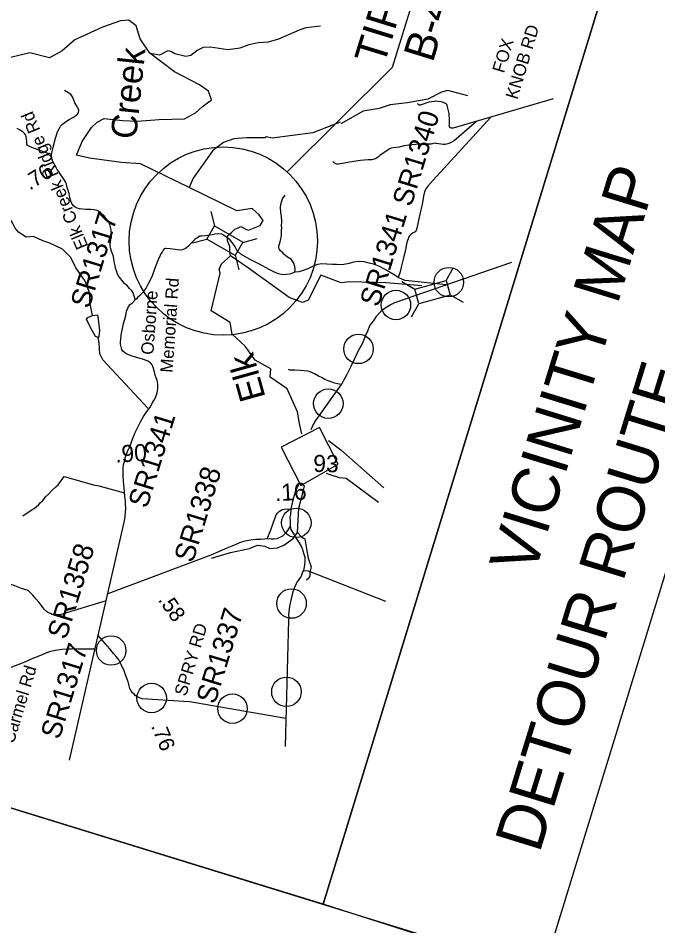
# Model space of a CAD drawing. Extents: x 1348011 to 1349268, y 1028333 to 1030014.
# Drawn here: x 1348154.1 to 1348346.3, y 1028708.2 to 1028980.8 of the extents above; entities that cross this region are included whole.
import ezdxf

# ---------------------------------------------------------------- set-up
doc = ezdxf.new("R2010")
doc.units = 0
for name, color, linetype in [('Prop Leader Line Light', 7, 'Continuous'), ('Prop Leader Line Medium', 7, 'Continuous'), ('Prop WCC CELL', 7, 'Continuous'), ('Scratch_Level_3', 7, 'Continuous'), ('Sheet Data Field CELL', 7, 'Continuous'), ('Sheet Symbology CELL', 7, 'Continuous')]:
    doc.layers.add(name, color=color, linetype=linetype)

msp = doc.modelspace()

# ---------------------------------------------------------------- linework, layer by layer
at = {"layer": 'Prop Leader Line Light'}
msp.add_lwpolyline([(1348302.35, 1028907.44), (1348267.14, 1028895.27), (1348266.17, 1028894.75), (1348264.42, 1028893.66), (1348263.06, 1028892.64), (1348261.7, 1028891.15), (1348260.73, 1028889.82), (1348259.82, 1028888.53), (1348259.04, 1028886.76), (1348258.46, 1028885.46), (1348257.43, 1028882.98), (1348256.2, 1028880.62), (1348255.1, 1028878.23), (1348253.98, 1028875.93), (1348252.76, 1028873.57), (1348251.78, 1028871.72), (1348251.42, 1028871.13), (1348251.18, 1028870.75), (1348243.41, 1028859.89), (1348242.72, 1028858.78), (1348242, 1028857.16)], dxfattribs=at)
for centre in [(1348283.51, 1028901.5), (1348267.61, 1028894.63), (1348256.37, 1028881.44), (1348247.29, 1028865.01), (1348237.7, 1028829.2), (1348236.26, 1028804.96), (1348182.07, 1028790.85), (1348234.71, 1028778.45), (1348194.21, 1028776.57), (1348218.5, 1028773.39)]:
    msp.add_circle(centre, 4.43, dxfattribs=at)
at = {"layer": 'Prop Leader Line Medium'}
for p, q in [((1348287.74, 1029034.54), (1348266.45, 1028965.92)), ((1348234.94, 1028934.6), (1348266.45, 1028965.92)), ((1348211.96, 1028922.74), (1348213.1, 1028918.41)), ((1348206.46, 1028913.31), (1348210.79, 1028914.45)), ((1348221.57, 1028913.44), (1348225.91, 1028914.58)), ((1348219.31, 1028909.57), (1348220.45, 1028905.23)), ((1348282.73, 1028902.01), (1348284.95, 1028905.9)), ((1348269.36, 1028901.64), (1348273.26, 1028899.43)), ((1348283.92, 1028897.68), (1348287.81, 1028895.46)), ((1348272.25, 1028891.11), (1348274.47, 1028895))]:
    msp.add_line(p, q, dxfattribs=at)
for points in [[(1348205.49, 1028929.9), (1348190.92, 1028937.03), (1348185.2, 1028937.42), (1348175.52, 1028938.7), (1348171.65, 1028939.62), (1348173.33, 1028943.77), (1348176.1, 1028947.9), (1348177.88, 1028949.58), (1348179.93, 1028950.63), (1348185.5, 1028950), (1348189.95, 1028949.82), (1348196.45, 1028950.36), (1348204.13, 1028950.58), (1348207.38, 1028952.32), (1348209.44, 1028954.13), (1348212.17, 1028956.21), (1348211.28, 1028958.89), (1348208.62, 1028960.8), (1348201.09, 1028964.63), (1348193.63, 1028970.29), (1348190.8, 1028974.54), (1348189.55, 1028978.48), (1348187.34, 1028980.13), (1348184.87, 1028980.02), (1348179.41, 1028978.04), (1348171.14, 1028974.26), (1348167.31, 1028970.94), (1348163.53, 1028968.84), (1348157.6, 1028970.38), (1348151.43, 1028968.83)], [(1348193.63, 1028970.29), (1348196.7, 1028969.77), (1348199.2, 1028971.04), (1348200.17, 1028970.81), (1348201.21, 1028970.17), (1348204.48, 1028969.32), (1348205.96, 1028969.67), (1348207.75, 1028971.05), (1348209.75, 1028972.06), (1348211.91, 1028972.19), (1348217.15, 1028971.36), (1348220.84, 1028971.82), (1348223.5, 1028972.83), (1348226.18, 1028973.5), (1348229.35, 1028973.64), (1348232.45, 1028974.58), (1348238.68, 1028977.31), (1348240.69, 1028977.99), (1348244.93, 1028978.48)], [(1348189.28, 1028896.17), (1348189.04, 1028897.12), (1348188.91, 1028897.62), (1348188.66, 1028898.27), (1348188.27, 1028898.85), (1348187.6, 1028899.59), (1348186.81, 1028900.55), (1348186.12, 1028901.02), (1348185.55, 1028901.7), (1348185.02, 1028902.37), (1348184.4, 1028903.17), (1348183.99, 1028903.94), (1348183.68, 1028904.9), (1348183.41, 1028905.74), (1348183.28, 1028906.43), (1348183.08, 1028907.23), (1348182.83, 1028908.43), (1348182.75, 1028909.22), (1348182.43, 1028910.03), (1348182.18, 1028910.76), (1348181.86, 1028911.78), (1348181.8, 1028912.61), (1348181.83, 1028913.67), (1348182.11, 1028915.08), (1348182.15, 1028916.01), (1348181.96, 1028917.63), (1348181.54, 1028919.2), (1348180.49, 1028920.74), (1348179.95, 1028921.38), (1348178.87, 1028922.4), (1348177.88, 1028923), (1348176.83, 1028923.24), (1348175.81, 1028923.34), (1348174.46, 1028923.36), (1348173.47, 1028923.44), (1348172.59, 1028923.56), (1348171.83, 1028923.69), (1348171.22, 1028924.05), (1348170.66, 1028924.5), (1348170.26, 1028925.13), (1348169.99, 1028925.77), (1348169.68, 1028926.88), (1348169.48, 1028928.13), (1348168.98, 1028929.61), (1348168.76, 1028930.18), (1348168.59, 1028931.02), (1348168.31, 1028931.66), (1348167.82, 1028932.45), (1348167.41, 1028933), (1348166.89, 1028933.7), (1348166.16, 1028934.9), (1348165.85, 1028935.34), (1348165.49, 1028935.94), (1348164.99, 1028936.82), (1348164.79, 1028937.22), (1348164.54, 1028937.69), (1348164.34, 1028938.34), (1348164.12, 1028939.07), (1348164.16, 1028939.44), (1348164.17, 1028939.87), (1348164.67, 1028941.99), (1348165.37, 1028944.75), (1348165.97, 1028946.64), (1348166.39, 1028947.58), (1348166.85, 1028948.32), (1348167.32, 1028948.86), (1348167.9, 1028949.3), (1348168.61, 1028949.82), (1348169.49, 1028950.32), (1348170.74, 1028951.03), (1348171.84, 1028951.87), (1348172.12, 1028952.23), (1348172.24, 1028952.36), (1348172.39, 1028953.12), (1348171.86, 1028954.23), (1348171.41, 1028954.84), (1348171.11, 1028955.37), (1348170.82, 1028956.2), (1348170.49, 1028957.18), (1348170.05, 1028957.74), (1348169.21, 1028958.33), (1348168.03, 1028959.04)], [(1348289.17, 1028957.45), (1348283.23, 1028959.02), (1348281.32, 1028958.6), (1348277.21, 1028956.47), (1348271.1, 1028955.33), (1348265.87, 1028954.78), (1348262.55, 1028953.61), (1348257.81, 1028952.88), (1348251.06, 1028949.07)], [(1348314.9, 1028956.52), (1348284.84, 1028947.76), (1348284.41, 1028947.71), (1348284.3, 1028947.74), (1348284.02, 1028947.86), (1348283.84, 1028947.98), (1348283.77, 1028948.07), (1348283.66, 1028948.24), (1348283.62, 1028948.44), (1348283.68, 1028949.06), (1348283.69, 1028949.16), (1348283.73, 1028950.16), (1348283.63, 1028952.14), (1348283.02, 1028954.5), (1348282.86, 1028954.87), (1348282.79, 1028954.95), (1348282.7, 1028955.01), (1348282.51, 1028955.11), (1348281.27, 1028955.61), (1348280.33, 1028955.78), (1348279.62, 1028955.81), (1348279.21, 1028955.79), (1348277.63, 1028955.55), (1348277.22, 1028955.43), (1348275.19, 1028954.73), (1348274.99, 1028954.69), (1348274.68, 1028954.67), (1348274.6, 1028954.73), (1348274.52, 1028954.79), (1348274.28, 1028954.99), (1348274.14, 1028955.09)], [(1348250.89, 1028949.51), (1348242.65, 1028946.37), (1348230.44, 1028944.77), (1348228.73, 1028945.16), (1348228.21, 1028944.83), (1348222.69, 1028944.88), (1348218.96, 1028944.53), (1348215.81, 1028943.47), (1348212.57, 1028941.06), (1348206.72, 1028932.71), (1348205.49, 1028929.9)], [(1348291.93, 1028949.82), (1348285.06, 1028943.91), (1348284.02, 1028943.35), (1348283.18, 1028943.06), (1348282.36, 1028942.85), (1348281.96, 1028942.79), (1348281.85, 1028942.79), (1348279.74, 1028943.18), (1348279.43, 1028943.2), (1348279.01, 1028943.17), (1348278.21, 1028942.95), (1348278, 1028942.9), (1348274.56, 1028942.91), (1348271.49, 1028942.65), (1348270.02, 1028942.44), (1348268.72, 1028942.07), (1348266.75, 1028941.85), (1348266.15, 1028941.69), (1348265.77, 1028941.53), (1348262.87, 1028939.62), (1348262.56, 1028939.36), (1348262.33, 1028939.14), (1348262.12, 1028938.93), (1348261.77, 1028938.72), (1348261.4, 1028938.55), (1348260.42, 1028938.23), (1348260.01, 1028938.19), (1348259.3, 1028938.22), (1348258.04, 1028938.16), (1348257.01, 1028938), (1348254.92, 1028937.73), (1348253.67, 1028937.49), (1348252.65, 1028937.3), (1348250.23, 1028936.89), (1348250.09, 1028936.88), (1348249.86, 1028936.94), (1348249.6, 1028937.02), (1348249.41, 1028937.14), (1348249.1, 1028937.33), (1348248.94, 1028937.43), (1348248.8, 1028937.58), (1348248.64, 1028937.73)], [(1348296.14, 1028951.05), (1348278.83, 1028932.12), (1348277.2, 1028930.32), (1348276.61, 1028929.51), (1348276.31, 1028928.85), (1348276.01, 1028927.78), (1348275.45, 1028924.88), (1348274.81, 1028921.88), (1348274.23, 1028919.07), (1348273.94, 1028917.66), (1348273.68, 1028917), (1348273.44, 1028916.62), (1348272.81, 1028916.32), (1348272.53, 1028916.12), (1348272.05, 1028915.81), (1348271.75, 1028915.46), (1348271.45, 1028915.06), (1348270.85, 1028913.37), (1348270.46, 1028911.29), (1348269.79, 1028908.41), (1348269.46, 1028907.24), (1348269.15, 1028906.01), (1348268.88, 1028904.55), (1348268.29, 1028902.93)], [(1348164.17, 1028939.87), (1348162.88, 1028940.26), (1348159.86, 1028941.34), (1348158.27, 1028941.93), (1348157.59, 1028942.24), (1348157.08, 1028942.46), (1348156.9, 1028942.62), (1348156.76, 1028942.95), (1348156.76, 1028943.51), (1348156.61, 1028944.69), (1348156.54, 1028945.17), (1348156.35, 1028945.69), (1348156.12, 1028946.03), (1348155.61, 1028946.59), (1348155.03, 1028946.93), (1348154.5, 1028947.26), (1348153.77, 1028947.65)], [(1348216.98, 1028914.79), (1348217.12, 1028915.51), (1348218.24, 1028916.39), (1348219.18, 1028917.41), (1348220.24, 1028917.84), (1348221.05, 1028918.25), (1348222.72, 1028917.32), (1348223.36, 1028917.08), (1348226.83, 1028918.48), (1348227.69, 1028919.97), (1348226.48, 1028921.76), (1348224.43, 1028923.64), (1348219.78, 1028922.95), (1348205.49, 1028929.9)], [(1348237.27, 1028904.45), (1348237.3, 1028905.39), (1348237.23, 1028906.1), (1348237.04, 1028907.04), (1348236.2, 1028908.33), (1348235.02, 1028909.04), (1348233.95, 1028909.94), (1348233.59, 1028910.31), (1348232.96, 1028910.88), (1348232.76, 1028911.17), (1348232.52, 1028911.53), (1348232.48, 1028911.9), (1348232.44, 1028912.4), (1348232.63, 1028912.92), (1348232.84, 1028913.62), (1348233.04, 1028914.49), (1348233.12, 1028914.86), (1348233.21, 1028915.64), (1348233.26, 1028917.02), (1348233.3, 1028917.67), (1348233.23, 1028918.39), (1348233.36, 1028919.56), (1348233.28, 1028921.3), (1348233.06, 1028922.45), (1348232.97, 1028924), (1348233.01, 1028924.75), (1348233.24, 1028925.63), (1348233.54, 1028926.52), (1348234.32, 1028927.65)], [(1348174.23, 1028901.81), (1348172.43, 1028904.35), (1348171.49, 1028905.82), (1348169.91, 1028908.88), (1348167.46, 1028911.35), (1348163.61, 1028913.23), (1348161.5, 1028913.92), (1348158.7, 1028915.16), (1348156.57, 1028915.02), (1348154.23, 1028916.54), (1348153.26, 1028917.68), (1348152.4, 1028919.26), (1348150.03, 1028922.86), (1348149.53, 1028923.24)], [(1348216.98, 1028914.79), (1348216.16, 1028915.34), (1348215.28, 1028915.86), (1348214.21, 1028915.97), (1348213.24, 1028915.9), (1348212.42, 1028915.71), (1348211.11, 1028915.54), (1348209.24, 1028915.31), (1348208.65, 1028915.27), (1348207.95, 1028914.85), (1348207.62, 1028914.65), (1348207.3, 1028914.36), (1348206.82, 1028913.89), (1348206.06, 1028913.21), (1348205.26, 1028912.34), (1348204.75, 1028911.9), (1348204.35, 1028911.58), (1348203.51, 1028911.17), (1348202.48, 1028911.14), (1348201.33, 1028911.26), (1348199.76, 1028911.48), (1348198.51, 1028911.64), (1348198.24, 1028911.64), (1348198.01, 1028911.52), (1348197.7, 1028911.07), (1348197.34, 1028910.52), (1348197, 1028909.95), (1348196.74, 1028909.53), (1348196.09, 1028908.03), (1348195.06, 1028905.37), (1348194.27, 1028903.09), (1348193.32, 1028901.14), (1348192.6, 1028899.83), (1348192, 1028898.94), (1348191.58, 1028898.43), (1348190.58, 1028897.42), (1348190.12, 1028896.98), (1348189.69, 1028896.52), (1348189.28, 1028896.17)], [(1348217.89, 1028909.44), (1348217.75, 1028910.7), (1348217.72, 1028912.18), (1348217.02, 1028913.9), (1348216.98, 1028914.79)], [(1348282.73, 1028900.66), (1348271.41, 1028901.9), (1348270.38, 1028902), (1348269.55, 1028902.26), (1348268.29, 1028902.93), (1348267.36, 1028903.53), (1348265.86, 1028904.43), (1348264.34, 1028905.33), (1348262.49, 1028906.3), (1348260.86, 1028906.89), (1348259.55, 1028907.23), (1348258.04, 1028907.6), (1348256.36, 1028907.7), (1348254.82, 1028907.5), (1348253.54, 1028907.12), (1348252, 1028906.81), (1348250.73, 1028906.71), (1348249.8, 1028906.77), (1348248.54, 1028906.83), (1348246.85, 1028906.9), (1348245.23, 1028907.03), (1348244.19, 1028906.75), (1348242.79, 1028906.33), (1348241.17, 1028905.48), (1348239.48, 1028904.9), (1348238.49, 1028904.62), (1348237.27, 1028904.45), (1348235.72, 1028903.93), (1348234.61, 1028903.79), (1348233.59, 1028903.68), (1348232.33, 1028904.01), (1348231.36, 1028904.44), (1348229.56, 1028905.28), (1348226.63, 1028906.86), (1348223.65, 1028908.4), (1348220.97, 1028909.94), (1348219.93, 1028910.88), (1348219.22, 1028912.27), (1348218.44, 1028913.41), (1348217.81, 1028914.13), (1348216.98, 1028914.79)], [(1348239.38, 1028855.94), (1348238.64, 1028859.08), (1348238.08, 1028862.57), (1348234.98, 1028869.48), (1348229.85, 1028873), (1348229.99, 1028875.49), (1348225.35, 1028878.1), (1348222.27, 1028882.28), (1348218.4, 1028885.86), (1348217.77, 1028889.34), (1348212.15, 1028892.9), (1348214.85, 1028904.19), (1348214.47, 1028905.34), (1348215.22, 1028907.01), (1348217.89, 1028909.44)], [(1348275.37, 1028900.41), (1348264.72, 1028901.26), (1348253.74, 1028901.57), (1348251.11, 1028901.32), (1348245.08, 1028903.6), (1348241.21, 1028896.11), (1348239.55, 1028895.43), (1348235.53, 1028896.92), (1348223.28, 1028905.69), (1348217.89, 1028909.44)], [(1348176.49, 1028891.48), (1348175.63, 1028895.51), (1348175.66, 1028898.13), (1348174.23, 1028901.81)], [(1348169.54, 1028757.92), (1348186.06, 1028829.8), (1348186.24, 1028831.11), (1348186.41, 1028832.31), (1348186.49, 1028833.57), (1348186.37, 1028834.8), (1348186.32, 1028835.57), (1348186.18, 1028837.25), (1348186.1, 1028838.54), (1348185.97, 1028839.78), (1348185.78, 1028841.57), (1348185.63, 1028843.51), (1348185.63, 1028844.53), (1348185.66, 1028845.64), (1348185.77, 1028846.66), (1348186.12, 1028848.06), (1348186.38, 1028849.07), (1348187, 1028850.61), (1348187.66, 1028852.11), (1348188.45, 1028854.31), (1348189.31, 1028856.37), (1348190.12, 1028857.98), (1348190.84, 1028859.5), (1348191.75, 1028861.16), (1348192.77, 1028862.62), (1348193.77, 1028863.92), (1348194.57, 1028865.44), (1348194.9, 1028865.92), (1348195.13, 1028866.38), (1348195.43, 1028867.16), (1348195.83, 1028868.25), (1348196.08, 1028869.43), (1348196.12, 1028870.32), (1348196.05, 1028870.89), (1348195.87, 1028872.07), (1348195.6, 1028872.78), (1348195.29, 1028873.51), (1348195.03, 1028874.51), (1348194.7, 1028875.82), (1348194.34, 1028876.61), (1348193.87, 1028877.22), (1348193.56, 1028877.44), (1348193.04, 1028877.81), (1348191.92, 1028878.25), (1348190.35, 1028878.62), (1348189.37, 1028878.92), (1348188.37, 1028879.25), (1348187.55, 1028879.57), (1348186.91, 1028879.84), (1348186.46, 1028880.05), (1348186.06, 1028880.32), (1348185.58, 1028880.81), (1348185.28, 1028881.28), (1348185.04, 1028882.07), (1348184.91, 1028882.83), (1348184.89, 1028883.55), (1348184.94, 1028884.36), (1348185.06, 1028885.6), (1348185.46, 1028887.55), (1348185.8, 1028889.06), (1348186.18, 1028890.33), (1348186.5, 1028891.52), (1348186.69, 1028892.75), (1348187.02, 1028893.64), (1348187.28, 1028894.18), (1348187.86, 1028894.83), (1348188.48, 1028895.33), (1348189.28, 1028896.17)], [(1348178.18, 1028884.89), (1348177.35, 1028885.16), (1348175.97, 1028887.69), (1348174.68, 1028890.41), (1348175.05, 1028890.91), (1348176.49, 1028891.48)], [(1348176.49, 1028891.48), (1348177.92, 1028891.64), (1348178.14, 1028890.4), (1348178.55, 1028886.94), (1348178.38, 1028885.12), (1348178.18, 1028884.89)], [(1348193.12, 1028863.64), (1348179.58, 1028878.18), (1348178.61, 1028879.95), (1348178.46, 1028883.21), (1348178.18, 1028884.89)], [(1348251.18, 1028870.75), (1348250.07, 1028870.94), (1348249.15, 1028871.2), (1348248.15, 1028871.57), (1348247.24, 1028871.86), (1348246.3, 1028872.29), (1348245.3, 1028872.82), (1348244.33, 1028873.3), (1348243.13, 1028873.94), (1348242.52, 1028874.26), (1348241.83, 1028874.57), (1348241.1, 1028874.76), (1348240.01, 1028874.86), (1348238.96, 1028874.96), (1348237.28, 1028875.04), (1348236.16, 1028875.07), (1348235.71, 1028875.09), (1348235.38, 1028875.24)], [(1348247.31, 1028853.96), (1348251.06, 1028851.16), (1348263.95, 1028839.74)], [(1348155.53, 1028831.31), (1348156.87, 1028832.23), (1348157.64, 1028832.75), (1348158.37, 1028833.22), (1348158.89, 1028833.46), (1348159.55, 1028834), (1348160.3, 1028834.67), (1348160.75, 1028835.21), (1348161.43, 1028835.83), (1348161.98, 1028836.51), (1348162.36, 1028836.99), (1348163.24, 1028837.85), (1348164.27, 1028838.87), (1348165.44, 1028839.98), (1348166.18, 1028840.63), (1348167.93, 1028843.11)], [(1348167.93, 1028843.11), (1348176.72, 1028840.58), (1348178.36, 1028840.33), (1348186.03, 1028838.17)], [(1348262.39, 1028835.27), (1348252.65, 1028842.49), (1348250.64, 1028842.73), (1348247.89, 1028843.63), (1348246.79, 1028844.04)], [(1348238.32, 1028840.58), (1348238.09, 1028840.13), (1348237.47, 1028838.77), (1348237, 1028837.39), (1348236.56, 1028835.57), (1348236.26, 1028834.26), (1348236.06, 1028833.27), (1348235.91, 1028831.82), (1348235.78, 1028830.78), (1348235.85, 1028829.86), (1348235.84, 1028829.28), (1348235.81, 1028828.21)], [(1348238.08, 1028826.31), (1348238.41, 1028833.59), (1348239.55, 1028837.78), (1348240.1, 1028840.27)], [(1348228.96, 1028824.37), (1348230.05, 1028827.08), (1348230.77, 1028829.13), (1348231.41, 1028830.96), (1348231.65, 1028831.65), (1348232.17, 1028832.23), (1348232.66, 1028832.67), (1348233.43, 1028833.17), (1348234.16, 1028833.35), (1348235.16, 1028833.36), (1348236.06, 1028833.27)], [(1348235.81, 1028828.21), (1348235.05, 1028826.89), (1348234.33, 1028825.97), (1348233.5, 1028825.17), (1348232.98, 1028824.94), (1348232.47, 1028824.65), (1348231.8, 1028824.41), (1348230.96, 1028824.26), (1348230.17, 1028824.27), (1348228.96, 1028824.37), (1348228.13, 1028824.26), (1348227, 1028824.23), (1348225.39, 1028824.15), (1348223.31, 1028823.91), (1348221.83, 1028823.59), (1348220.62, 1028823.19), (1348219.55, 1028822.71), (1348217.82, 1028822.01), (1348216.27, 1028821.35), (1348214.31, 1028820.45), (1348212.02, 1028819.52), (1348181.03, 1028807.91)], [(1348212.2, 1028818.58), (1348217.92, 1028820.34), (1348223.59, 1028821.49), (1348226.04, 1028822.48), (1348228.24, 1028822.18), (1348229.77, 1028821.52), (1348232.07, 1028821.68), (1348233.91, 1028822.46), (1348236.77, 1028824.45), (1348238.08, 1028826.31)], [(1348235.81, 1028828.21), (1348236.08, 1028827.19), (1348236.95, 1028825.8), (1348237.71, 1028824.43), (1348238.51, 1028823.15), (1348239.23, 1028821.95), (1348239.54, 1028821.22), (1348239.68, 1028820.78), (1348239.97, 1028819.84), (1348240.2, 1028818.93), (1348240.29, 1028817.93), (1348240.18, 1028816.45), (1348239.85, 1028814.91), (1348239.69, 1028814.58), (1348239.47, 1028814.07), (1348239.13, 1028813.23), (1348238.29, 1028811.93), (1348237.86, 1028811.36)], [(1348238.08, 1028826.31), (1348239.21, 1028825.03), (1348240.22, 1028824.36), (1348240.78, 1028821.42), (1348241.26, 1028818.62), (1348242.14, 1028815.95), (1348241.79, 1028814.36), (1348241.78, 1028813.16), (1348241.33, 1028812.45), (1348240.74, 1028811.96)], [(1348239.85, 1028814.91), (1348241.29, 1028814.76), (1348264.47, 1028805.69)], [(1348141.2, 1028806.99), (1348145.08, 1028810.92), (1348146.1, 1028811.48), (1348147.19, 1028811.88), (1348147.76, 1028811.88), (1348148.35, 1028811.94), (1348149.05, 1028811.9), (1348149.88, 1028811.7), (1348150.6, 1028811.38), (1348151.67, 1028810.8), (1348152.47, 1028810.57), (1348153.52, 1028810.15), (1348155.03, 1028809.58), (1348157.03, 1028808.97)], [(1348237.86, 1028811.36), (1348237.64, 1028810.91), (1348237.01, 1028809.55), (1348236.54, 1028808.17), (1348236.1, 1028806.35), (1348235.8, 1028805.04), (1348235.61, 1028804.05), (1348235.45, 1028802.61), (1348235.33, 1028801.56), (1348235.4, 1028800.64), (1348235.38, 1028800.07), (1348234.34, 1028762.03)], [(1348180.54, 1028805.78), (1348166.6, 1028801.54), (1348165.44, 1028801.54), (1348164.29, 1028801.71), (1348163.79, 1028801.98), (1348163.25, 1028802.21), (1348162.64, 1028802.58), (1348162.02, 1028803.16), (1348161.53, 1028803.78), (1348160.87, 1028804.8), (1348160.28, 1028805.39), (1348159.56, 1028806.26), (1348158.5, 1028807.48), (1348157.03, 1028808.97)], [(1348203.92, 1028775.58), (1348191.41, 1028776.37), (1348190.32, 1028776.78), (1348189.31, 1028777.34), (1348188.94, 1028777.77), (1348188.5, 1028778.17), (1348188.07, 1028778.74), (1348187.69, 1028779.49), (1348187.45, 1028780.25), (1348187.19, 1028781.44), (1348186.84, 1028782.2), (1348186.47, 1028783.26), (1348185.92, 1028784.78), (1348185.06, 1028786.69), (1348184.32, 1028788.01), (1348183.58, 1028789.05), (1348182.8, 1028789.93), (1348181.62, 1028791.36), (1348178.16, 1028795.41)], [(1348177.2, 1028791.24), (1348172.17, 1028791.25), (1348170.95, 1028791.36), (1348170.13, 1028791.25), (1348169, 1028791.22), (1348167.38, 1028791.14), (1348165.3, 1028790.89), (1348163.83, 1028790.58), (1348162.62, 1028790.18), (1348161.54, 1028789.7), (1348159.82, 1028789), (1348158.27, 1028788.34), (1348156.31, 1028787.43), (1348154.01, 1028786.51), (1348137.34, 1028780.26)], [(1348203.92, 1028775.58), (1348205.05, 1028775.66), (1348234.57, 1028770.51)]]:
    msp.add_lwpolyline(points, dxfattribs=at)
for points in [[(1348213.1, 1028918.41), (1348221.58, 1028913.46), (1348219.27, 1028909.5), (1348210.79, 1028914.45)], [(1348273.26, 1028899.43), (1348282.73, 1028902.03), (1348283.94, 1028897.6), (1348274.47, 1028895)]]:
    msp.add_lwpolyline(points, close=True, dxfattribs=at)
msp.add_circle((1348215.74, 1028913.84), 28.28, dxfattribs=at)
at = {"layer": 'Prop WCC CELL'}
for points in [[(1348067.18, 1028769.65), (1348163, 1029082), (1348341.6, 1029027), (1348245.78, 1028714.65)], [(1348245.78, 1028714.65), (1348341.6, 1029027), (1348407.4, 1029005.91), (1348311.58, 1028693.56)]]:
    msp.add_lwpolyline(points, close=True, dxfattribs=at)
at = {"layer": 'Scratch_Level_3'}
msp.add_line((1348067.18, 1028769.65), (1348711.01, 1028571.38), dxfattribs=at)
at = {"layer": 'Sheet Symbology CELL'}
msp.add_lwpolyline([(1348233.18, 1028851.95), (1348239.03, 1028840.41), (1348250.29, 1028846.8), (1348244.68, 1028857.81)], close=True, dxfattribs=at)

# ---------------------------------------------------------------- texts
at = {"layer": 'Prop Leader Line Light'}
for s, height, rotation, p in [('Creek', 7.701, 84.0306, (1348189.53, 1028944.2)), ('SR1340', 6.055, 72.8834, (1348272.2, 1028923.87)), ('.76', 4.62, 32.3474, (1348157.62, 1028928.96)), ('VICINITY MAP', 14.1752, 72.8834, (1348309.05, 1028812.96)), ('SR1317', 6.055, 72.8834, (1348175.47, 1028893.27)), ('SR1341', 6.055, 72.8834, (1348262.41, 1028893.76)), ('Elk', 7.701, 105.5962, (1348228.49, 1028866.9)), ('DETOUR ROUTE', 14.1752, 72.8834, (1348310.71, 1028729.68)), ('SR1341', 6.055, 72.8834, (1348192.84, 1028833.3)), ('.90', 5.134, 3.2667, (1348183.38, 1028847.27)), ('SR1338', 6.055, 72.8834, (1348206.62, 1028816.94)), ('.16', 5.134, 3.2667, (1348231.36, 1028835.67)), ('SR1358', 6.055, 72.8834, (1348168.53, 1028793.85)), ('.58', 4.62, 304.5742, (1348196.02, 1028806.07)), ('SR1337', 6.055, 72.8834, (1348213.25, 1028774.46)), ('SR1317', 6.055, 72.8834, (1348166.52, 1028763.85)), ('.76', 4.62, 292.3701, (1348193.94, 1028768.16))]:
    msp.add_text(s, height=height, rotation=rotation, dxfattribs=at).set_placement(p)
at = {"layer": 'Prop Leader Line Medium'}
for s, height, rotation, p in [('KNOB RD', 3.763, 73.1908, (1348304.06, 1028956.16)), ('FOX', 3.763, 73.1908, (1348300.07, 1028964.07)), ('Elk Creek Ridge Rd', 3.7631, 112.4407, (1348175.24, 1028912.28)), ('Memorial Rd', 3.7631, 86.0569, (1348200.5, 1028874.2)), ('Osborne ', 3.763, 86.0569, (1348194.74, 1028879.59)), ('93', 5.134, 359.1116, (1348242.74, 1028844.5)), ('SPRY RD', 3.763, 73.1908, (1348204.56, 1028776.93)), ('Carmel Rd', 3.763, 73.1908, (1348152.77, 1028762.64))]:
    msp.add_text(s, height=height, rotation=rotation, dxfattribs=at).set_placement(p)
at = {"layer": 'Sheet Data Field CELL'}
for s, p in [('TIP PROJECT', (1348263.96, 1028966.2)), ('B-4701', (1348278.66, 1028967.2))]:
    msp.add_text(s, height=9.344, rotation=72.8834, dxfattribs=at).set_placement(p)

doc.saveas('drawing.dxf')
